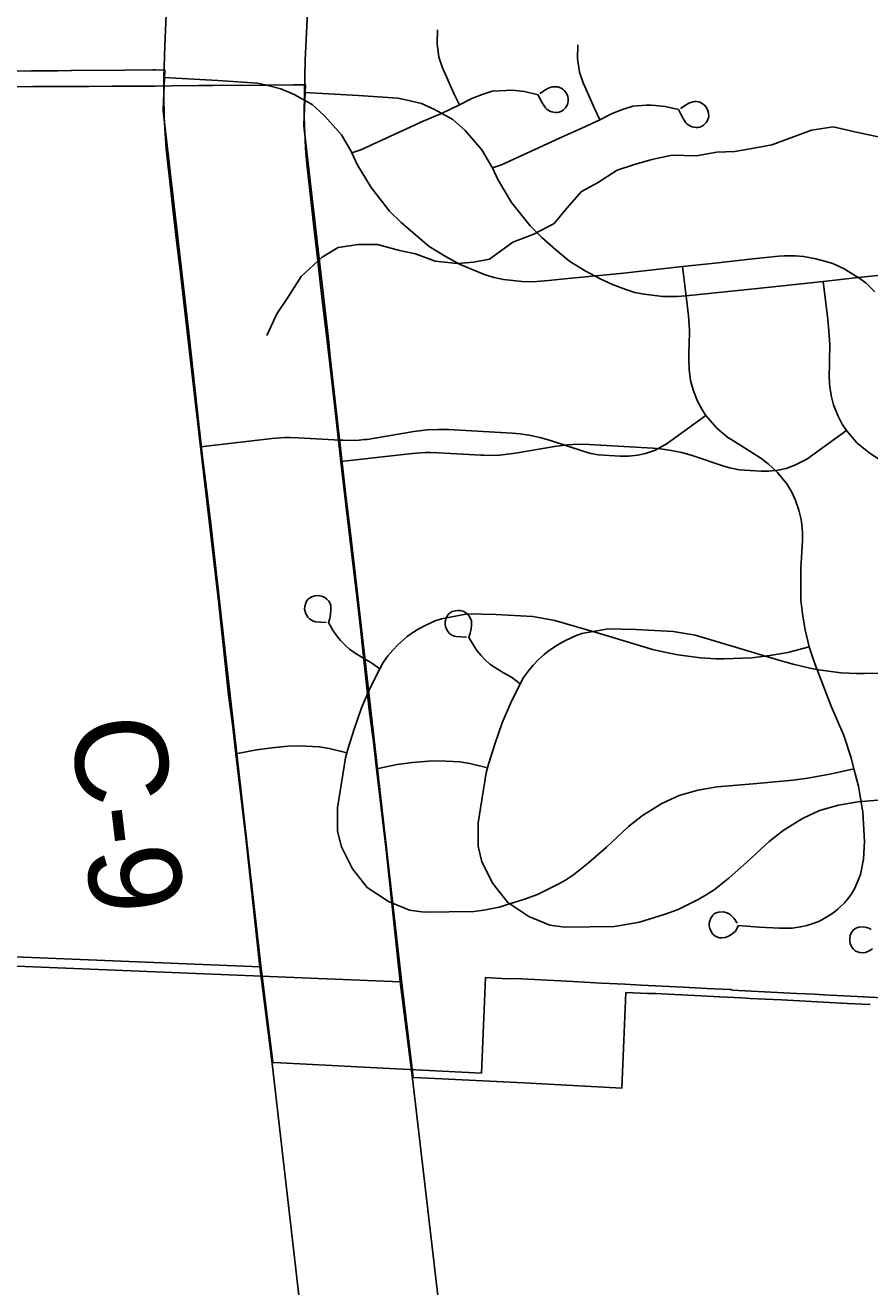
# Model space of a CAD drawing. Extents: x -38.2 to 41.9, y -4 to 24.9.
# Drawn here: x 6.95 to 7.47, y 18.257 to 19.034 of the extents above; entities that cross this region are included whole.
import ezdxf

# ---------------------------------------------------------------- set-up
doc = ezdxf.new("R2010")
doc.units = 0
for name, color, linetype in [('Default', 7, 'Continuous'), ('GM_X_City_Street', 7, 'Continuous'), ('GM_X_County_Road', 7, 'Continuous'), ('GM_X_County_Road_Text', 7, 'Continuous'), ('GM_X_Interstate_Location', 7, 'Continuous'), ('GM_X_Minor_River', 7, 'Continuous'), ('GM_X_State_Location', 7, 'Continuous'), ('GM_X_Township_Road', 7, 'Continuous'), ('GM_X_Township_Road_Text', 7, 'Continuous')]:
    doc.layers.add(name, color=color, linetype=linetype)

msp = doc.modelspace()

# ---------------------------------------------------------------- linework, layer by layer
at = {"layer": 'Default'}
msp.add_lwpolyline([(7.497, 18.43424), (7.46218, 18.436), (7.44131, 18.43708), (7.43595, 18.43734), (7.42495, 18.4379), (7.41694, 18.43831), (7.38512, 18.43992), (7.38471, 18.44022), (7.38362, 18.44027), (7.37894, 18.44049), (7.36978, 18.44096), (7.35502, 18.44171), (7.32916, 18.44303), (7.31911, 18.44354), (7.3097, 18.44401), (7.30457, 18.44427), (7.29085, 18.44497), (7.27963, 18.44554), (7.27144, 18.44596), (7.25156, 18.44697), (7.24675, 18.44696), (7.23335, 18.44764), (7.23212, 18.41809), (7.23092, 18.38882), (7.17044, 18.39194), (7.10733, 18.39511), (7.10279, 18.39533), (7.10252, 18.39535), (7.10249, 18.39557), (7.09519, 18.45511), (7.07983, 18.59072), (7.07899, 18.59787), (7.07242, 18.65558), (7.06436, 18.72708), (7.06082, 18.75528), (7.05954, 18.76639), (7.05681, 18.79004), (7.05223, 18.83156), (7.05142, 18.83892), (7.05024, 18.85002), (7.03554, 18.97766), (7.03508, 18.98152), (7.03511, 18.98205), (7.03617, 19.00643), (7.03589, 19.00644), (7.0302, 19.00651), (7.02868, 19.00649), (7.01151, 19.00636), (6.97904, 19.0061), (6.97833, 19.0061), (6.97031, 19.00602), (6.95401, 19.00585), (6.94344, 19.00575)], dxfattribs=at)
at = {"layer": 'GM_X_City_Street'}
msp.add_lwpolyline([(6.74985, 18.47012), (6.84845, 18.46426), (7.09446, 18.4542)], dxfattribs=at)
at = {"layer": 'GM_X_County_Road'}
for p, q in [((7.06148, 18.7446), (7.05794, 18.77452)), ((7.10206, 18.39474), (7.09446, 18.4542)), ((7.12619, 18.18681), (7.10206, 18.39474))]:
    msp.add_line(p, q, dxfattribs=at)
for points in [[(7.03553, 19.00186), (7.03605, 19.02162), (7.03797, 19.06405), (7.03985, 19.10826), (7.04183, 19.15386), (7.04831, 19.29914)], [(7.05794, 18.77452), (7.05354, 18.81334), (7.05063, 18.83833), (7.04624, 18.87594), (7.04521, 18.88496), (7.04348, 18.8997), (7.0411, 18.92093), (7.03977, 18.9322), (7.03694, 18.95784), (7.03618, 18.96745), (7.03574, 18.97735), (7.03564, 18.98011), (7.03536, 18.98816), (7.03553, 19.00186)], [(7.47009, 18.43109), (7.46542, 18.4313), (7.45626, 18.43177), (7.4415, 18.43252), (7.41564, 18.43384), (7.40559, 18.43435), (7.39618, 18.43483), (7.39104, 18.43508), (7.37733, 18.43578), (7.36611, 18.43636), (7.35792, 18.43677), (7.33803, 18.43778), (7.33323, 18.43777), (7.31983, 18.43845), (7.3186, 18.4089), (7.3174, 18.37963), (7.25692, 18.38275), (7.1938, 18.38592), (7.18927, 18.38615), (7.189, 18.38616), (7.18897, 18.38638), (7.18167, 18.44592), (7.16631, 18.58153), (7.16547, 18.58868), (7.1589, 18.64639), (7.15083, 18.71789), (7.1473, 18.74609), (7.14602, 18.7572), (7.14329, 18.78085), (7.13871, 18.82237), (7.1379, 18.82973), (7.13672, 18.84083), (7.12201, 18.96847), (7.12156, 18.97234), (7.12159, 18.97286), (7.12265, 18.99724), (7.12236, 18.99725), (7.11668, 18.99732), (7.11516, 18.9973), (7.09799, 18.99717), (7.06552, 18.99691), (7.06481, 18.99691), (7.05679, 18.99683), (7.04048, 18.99666), (7.02992, 18.99656), (7.02344, 18.99653), (7.02019, 18.99652), (7.00723, 18.99646), (7.00371, 18.99645), (6.98922, 18.99638), (6.97205, 18.9963), (6.96454, 18.99626), (6.95483, 18.99621), (6.94327, 18.99616)], [(7.09446, 18.4542), (7.08571, 18.53548), (7.0798, 18.58533), (7.078, 18.60202), (7.0753, 18.6217), (7.06938, 18.67779), (7.06148, 18.7446)]]:
    msp.add_lwpolyline(points, dxfattribs=at)
at = {"layer": 'GM_X_Interstate_Location'}
msp.add_lwpolyline([(6.83633, 18.46093), (6.93493, 18.45507), (7.18094, 18.44501)], dxfattribs=at)
at = {"layer": 'GM_X_Minor_River'}
for points in [[(7.43411, 18.96948), (7.41973, 18.96418), (7.40951, 18.96039), (7.39968, 18.9585), (7.38681, 18.95623), (7.37583, 18.95586), (7.36297, 18.95359), (7.34821, 18.95397), (7.33572, 18.95132), (7.32512, 18.9483), (7.31453, 18.94489), (7.30242, 18.93693), (7.29258, 18.93162), (7.2835, 18.92139), (7.27556, 18.91191), (7.26307, 18.90547), (7.25021, 18.90055), (7.23583, 18.88994), (7.22599, 18.88804), (7.21615, 18.88729), (7.20253, 18.88881), (7.19041, 18.89337), (7.18057, 18.89527), (7.16695, 18.89907), (7.15522, 18.89907), (7.14273, 18.89718), (7.13289, 18.89112), (7.12003, 18.87937), (7.11171, 18.86648), (7.1049, 18.85624), (7.09885, 18.84298)], [(7.47498, 18.9653), (7.4606, 18.96834), (7.44736, 18.97138), (7.43411, 18.96948)]]:
    msp.add_lwpolyline(points, dxfattribs=at)
at = {"layer": 'GM_X_State_Location'}
for points in [[(7.30383, 18.97586), (7.30065, 18.98237), (7.29349, 18.99853), (7.29127, 19.00511), (7.29009, 19.01351), (7.29026, 19.02192)], [(7.12201, 18.99267), (7.1552, 18.99074), (7.17955, 18.98907), (7.18435, 18.98816), (7.19397, 18.98578), (7.20211, 18.98212), (7.21321, 18.97599), (7.22081, 18.96912), (7.23117, 18.95733), (7.23671, 18.94789)], [(7.23771, 18.94617), (7.24322, 18.9481), (7.2816, 18.9657), (7.29271, 18.97055), (7.30383, 18.97586), (7.31143, 18.9797), (7.31779, 18.98212), (7.32403, 18.98421), (7.3323, 18.98473), (7.33521, 18.98477), (7.33812, 18.98464), (7.34389, 18.98396), (7.35223, 18.98208)], [(7.35223, 18.98208), (7.35362, 18.97928), (7.35513, 18.97655), (7.35675, 18.97394), (7.35759, 18.97314), (7.35853, 18.97246), (7.35956, 18.97191), (7.36064, 18.97149), (7.36177, 18.97122), (7.36293, 18.9711), (7.36409, 18.97113), (7.36523, 18.97131), (7.36674, 18.97192), (7.36765, 18.97251), (7.3692, 18.97405), (7.36979, 18.97497), (7.37025, 18.97595), (7.37057, 18.97699), (7.37074, 18.97807), (7.37071, 18.97976), (7.37049, 18.98087), (7.36962, 18.98296), (7.36823, 18.98473), (7.36737, 18.98547), (7.36642, 18.98609), (7.3654, 18.98657), (7.36453, 18.98685), (7.36332, 18.98701), (7.36211, 18.987), (7.36089, 18.98685), (7.35971, 18.98655), (7.35858, 18.9861), (7.35751, 18.98552), (7.35679, 18.98501), (7.35341, 18.98283)], [(7.23671, 18.94789), (7.23771, 18.94617), (7.24092, 18.93901), (7.24943, 18.92491), (7.26086, 18.91043), (7.26803, 18.90329), (7.2767, 18.89582), (7.28529, 18.8886), (7.29469, 18.88276), (7.30394, 18.87779), (7.31164, 18.87441), (7.3197, 18.87124), (7.32527, 18.86951), (7.331, 18.86835), (7.34248, 18.86708), (7.3478, 18.8669), (7.35146, 18.86698), (7.35873, 18.86759), (7.36874, 18.86864), (7.40478, 18.87228), (7.44111, 18.87631), (7.46095, 18.87842), (7.48448, 18.88092)], [(7.4451, 18.82437), (7.44519, 18.82764), (7.44538, 18.83711), (7.44472, 18.84593), (7.44404, 18.85279), (7.44111, 18.87631)], [(7.45557, 18.78448), (7.45296, 18.78848), (7.45018, 18.79376), (7.44765, 18.80025), (7.44613, 18.80603), (7.44512, 18.81293), (7.44493, 18.81892), (7.4451, 18.82437)], [(7.14441, 18.76533), (7.18851, 18.77037), (7.19632, 18.77094), (7.19962, 18.77098), (7.20457, 18.77083), (7.23055, 18.76934), (7.2322, 18.76926), (7.23715, 18.76919), (7.24209, 18.76939), (7.24539, 18.76966), (7.24703, 18.76984), (7.25186, 18.77054), (7.27581, 18.77466), (7.28392, 18.77569), (7.29052, 18.776), (7.29713, 18.77586), (7.33631, 18.77362), (7.34117, 18.77321), (7.34771, 18.77226), (7.35417, 18.77086), (7.36051, 18.76901), (7.38064, 18.76235), (7.38462, 18.76123), (7.3895, 18.76035), (7.39275, 18.76005), (7.40283, 18.75947), (7.40779, 18.75944), (7.41354, 18.76008), (7.41838, 18.76117), (7.42384, 18.76309), (7.43116, 18.76694), (7.45557, 18.78448)], [(7.51403, 18.69072), (7.51404, 18.69369), (7.51497, 18.70765), (7.51503, 18.71163), (7.51481, 18.71561), (7.51415, 18.72053), (7.5128, 18.72635), (7.51046, 18.73291), (7.50831, 18.73739), (7.50523, 18.74249), (7.49966, 18.74947), (7.49384, 18.75487), (7.4886, 18.75862), (7.4714, 18.76951), (7.46904, 18.77109), (7.46216, 18.77679), (7.45557, 18.78448)], [(7.22179, 18.65715), (7.21536, 18.65759), (7.21409, 18.65788), (7.21271, 18.65848), (7.21148, 18.65935), (7.21045, 18.66045), (7.20966, 18.66173), (7.20934, 18.66236), (7.20882, 18.66381), (7.2086, 18.66534), (7.20867, 18.66688), (7.20924, 18.66903), (7.20983, 18.6703), (7.21068, 18.6714), (7.21175, 18.6723), (7.21299, 18.67295), (7.21492, 18.67347), (7.21646, 18.67368), (7.21802, 18.67359), (7.21964, 18.67316), (7.22107, 18.67242), (7.22233, 18.67143), (7.2234, 18.67022), (7.22421, 18.66883), (7.22475, 18.66731), (7.22481, 18.66488), (7.22458, 18.66223), (7.22405, 18.65962), (7.22323, 18.65708), (7.22594, 18.65236), (7.22815, 18.64913), (7.2306, 18.6461), (7.23327, 18.64326), (7.23616, 18.64064), (7.2396, 18.63827), (7.24443, 18.63526), (7.24941, 18.63252), (7.25476, 18.6286)], [(7.23458, 18.57675), (7.2354, 18.57973), (7.23909, 18.59136), (7.24362, 18.60452), (7.24874, 18.61641), (7.25476, 18.6286), (7.25681, 18.63251), (7.25982, 18.63659), (7.26282, 18.6401), (7.26604, 18.64342), (7.26948, 18.6465), (7.27176, 18.64837), (7.27525, 18.65091), (7.27892, 18.65319), (7.28273, 18.65522), (7.28888, 18.65807), (7.2927, 18.65941), (7.30882, 18.66244), (7.32618, 18.66192), (7.34899, 18.66076), (7.36247, 18.65839), (7.38937, 18.65054), (7.41252, 18.64348), (7.42272, 18.64053), (7.43307, 18.63817), (7.43829, 18.63722), (7.45222, 18.63534), (7.46176, 18.63481), (7.46653, 18.63477), (7.48371, 18.63533)], [(7.16627, 18.57614), (7.17898, 18.57878), (7.1884, 18.58), (7.19829, 18.58099), (7.20478, 18.58119), (7.20926, 18.58093), (7.21763, 18.58047), (7.22374, 18.57942), (7.23458, 18.57675)], [(7.23458, 18.57675), (7.23375, 18.57379), (7.22882, 18.543), (7.22882, 18.52857), (7.23123, 18.51895), (7.23796, 18.50548), (7.24711, 18.49395), (7.2601, 18.48529), (7.27309, 18.47993), (7.28215, 18.47866), (7.31275, 18.47917), (7.31877, 18.48004), (7.32821, 18.48186), (7.34391, 18.48668), (7.35194, 18.48965), (7.36462, 18.49593), (7.3691, 18.49849), (7.37403, 18.50175), (7.38336, 18.509), (7.39429, 18.51869), (7.40793, 18.53139), (7.4166, 18.53825), (7.42849, 18.54554), (7.43897, 18.55046), (7.45061, 18.55375), (7.46246, 18.55585), (7.48459, 18.55777)], [(7.47069, 18.47716), (7.46933, 18.478), (7.46784, 18.47857), (7.46627, 18.47885), (7.46318, 18.47874), (7.46188, 18.47837), (7.46069, 18.47772), (7.45967, 18.47683), (7.45851, 18.47496), (7.45791, 18.47345), (7.45759, 18.47187), (7.45757, 18.47025), (7.45786, 18.46866), (7.45885, 18.46641), (7.45981, 18.4652), (7.46098, 18.46421), (7.46233, 18.46347), (7.46379, 18.46301), (7.46532, 18.46283), (7.46727, 18.46306), (7.46945, 18.46403), (7.47148, 18.46527)]]:
    msp.add_lwpolyline(points, dxfattribs=at)
at = {"layer": 'GM_X_Township_Road'}
for points in [[(7.21735, 18.98505), (7.21417, 18.99156), (7.20702, 19.00772), (7.20479, 19.0143), (7.20361, 19.0227), (7.20378, 19.03111)], [(7.03553, 19.00186), (7.06872, 18.99993), (7.09308, 18.99826), (7.09787, 18.99735), (7.10749, 18.99497), (7.11564, 18.99131), (7.12673, 18.98518), (7.13433, 18.97831), (7.14469, 18.96652), (7.15023, 18.95708)], [(7.15124, 18.95536), (7.15675, 18.95729), (7.19512, 18.97489), (7.20623, 18.97974), (7.21735, 18.98505), (7.22495, 18.98888), (7.23131, 18.99131), (7.23755, 18.9934), (7.24583, 18.99392), (7.24873, 18.99396), (7.25164, 18.99383), (7.25742, 18.99315), (7.26575, 18.99127)], [(7.26575, 18.99127), (7.26714, 18.98847), (7.26866, 18.98573), (7.27027, 18.98312), (7.27112, 18.98233), (7.27205, 18.98165), (7.27308, 18.9811), (7.27416, 18.98068), (7.27529, 18.98041), (7.27645, 18.98029), (7.27761, 18.98032), (7.27875, 18.9805), (7.28026, 18.98111), (7.28118, 18.9817), (7.28272, 18.98324), (7.28331, 18.98416), (7.28377, 18.98514), (7.28409, 18.98618), (7.28426, 18.98726), (7.28423, 18.98895), (7.28402, 18.99006), (7.28315, 18.99215), (7.28175, 18.99392), (7.2809, 18.99466), (7.27995, 18.99528), (7.27892, 18.99576), (7.27806, 18.99604), (7.27685, 18.9962), (7.27563, 18.99619), (7.27442, 18.99604), (7.27324, 18.99574), (7.2721, 18.99529), (7.27103, 18.99471), (7.27031, 18.9942), (7.26693, 18.99202)], [(7.15023, 18.95708), (7.15124, 18.95536), (7.15444, 18.9482), (7.16295, 18.9341), (7.17438, 18.91962), (7.18155, 18.91248), (7.19023, 18.90501), (7.19881, 18.89779), (7.20822, 18.89194), (7.21746, 18.88698), (7.22516, 18.8836), (7.23322, 18.88043), (7.23879, 18.8787), (7.24452, 18.87754), (7.256, 18.87627), (7.26132, 18.87609), (7.26498, 18.87617), (7.27225, 18.87678), (7.28226, 18.87783), (7.3183, 18.88147), (7.35463, 18.88549), (7.37448, 18.88761), (7.398, 18.89011), (7.41383, 18.89188), (7.41728, 18.89209), (7.42419, 18.89206), (7.4291, 18.89167), (7.43677, 18.89024), (7.4443, 18.88823), (7.44713, 18.88731), (7.45402, 18.88405), (7.46383, 18.87816), (7.46764, 18.87521), (7.47309, 18.8699)], [(7.35862, 18.83356), (7.35872, 18.83683), (7.3589, 18.8463), (7.35825, 18.85512), (7.35756, 18.86198), (7.35463, 18.88549)], [(7.36909, 18.79367), (7.36648, 18.79766), (7.3637, 18.80295), (7.36117, 18.80944), (7.35965, 18.81522), (7.35864, 18.82212), (7.35846, 18.82811), (7.35862, 18.83356)], [(7.05794, 18.77452), (7.10203, 18.77956), (7.10984, 18.78013), (7.11315, 18.78017), (7.11809, 18.78002), (7.14407, 18.77853), (7.14572, 18.77845), (7.15067, 18.77838), (7.15562, 18.77858), (7.15891, 18.77885), (7.16055, 18.77903), (7.16538, 18.77973), (7.18933, 18.78385), (7.19745, 18.78488), (7.20405, 18.78519), (7.21065, 18.78505), (7.24983, 18.78281), (7.25469, 18.7824), (7.26124, 18.78145), (7.26769, 18.78005), (7.27404, 18.7782), (7.29416, 18.77154), (7.29814, 18.77042), (7.30302, 18.76953), (7.30627, 18.76924), (7.31635, 18.76866), (7.32131, 18.76863), (7.32706, 18.76927), (7.3319, 18.77036), (7.33737, 18.77228), (7.34468, 18.77613), (7.36909, 18.79367)], [(7.42755, 18.69991), (7.42757, 18.70287), (7.4285, 18.71684), (7.42855, 18.72082), (7.42834, 18.7248), (7.42768, 18.72972), (7.42632, 18.73554), (7.42399, 18.7421), (7.42184, 18.74658), (7.41875, 18.75168), (7.41318, 18.75866), (7.40736, 18.76406), (7.40212, 18.76781), (7.38492, 18.7787), (7.38256, 18.78028), (7.37569, 18.78598), (7.36909, 18.79367)], [(7.38824, 18.48108), (7.38633, 18.48398), (7.38421, 18.48635), (7.38285, 18.48719), (7.38137, 18.48776), (7.37979, 18.48804), (7.37671, 18.48793), (7.3754, 18.48756), (7.37421, 18.48691), (7.3732, 18.48602), (7.37203, 18.48415), (7.37143, 18.48264), (7.37111, 18.48106), (7.3711, 18.47944), (7.37138, 18.47785), (7.37238, 18.4756), (7.37333, 18.47439), (7.37451, 18.4734), (7.37585, 18.47266), (7.37731, 18.4722), (7.37884, 18.47202), (7.38079, 18.47225), (7.38297, 18.47322), (7.385, 18.47446), (7.38725, 18.4763), (7.38908, 18.47964), (7.40185, 18.47877), (7.41432, 18.4781), (7.42233, 18.47814), (7.4233, 18.47824), (7.4273, 18.47885), (7.43123, 18.47976), (7.43508, 18.48096), (7.43884, 18.48244), (7.44391, 18.48519), (7.44718, 18.48738), (7.45026, 18.48983), (7.45428, 18.49366), (7.45658, 18.49635), (7.45865, 18.49923), (7.46046, 18.50228), (7.462, 18.50547), (7.46408, 18.51106), (7.46604, 18.52053), (7.46664, 18.53146), (7.46558, 18.54945), (7.46288, 18.56542), (7.46017, 18.57625), (7.45849, 18.58291), (7.45399, 18.59675), (7.44621, 18.61471), (7.43891, 18.63345), (7.43559, 18.64211), (7.43267, 18.65134), (7.43022, 18.6617), (7.42873, 18.67012), (7.42745, 18.68011), (7.42755, 18.69991)], [(7.13531, 18.66634), (7.12889, 18.66678), (7.12761, 18.66707), (7.12623, 18.66767), (7.125, 18.66854), (7.12398, 18.66964), (7.12319, 18.67092), (7.12286, 18.67154), (7.12234, 18.673), (7.12212, 18.67453), (7.12219, 18.67607), (7.12276, 18.67822), (7.12335, 18.67949), (7.1242, 18.68059), (7.12527, 18.68149), (7.12651, 18.68214), (7.12844, 18.68266), (7.12998, 18.68287), (7.13154, 18.68278), (7.13316, 18.68234), (7.13459, 18.6816), (7.13586, 18.68062), (7.13692, 18.67941), (7.13773, 18.67802), (7.13827, 18.6765), (7.13833, 18.67407), (7.1381, 18.67141), (7.13757, 18.6688), (7.13675, 18.66627), (7.13947, 18.66155), (7.14167, 18.65832), (7.14412, 18.65529), (7.14679, 18.65245), (7.14968, 18.64983), (7.15312, 18.64746), (7.15795, 18.64445), (7.16294, 18.64171), (7.16828, 18.63779)], [(7.1481, 18.58594), (7.14892, 18.58892), (7.15261, 18.60055), (7.15714, 18.61371), (7.16227, 18.6256), (7.16828, 18.63779), (7.17033, 18.6417), (7.17334, 18.64578), (7.17635, 18.64929), (7.17956, 18.65261), (7.183, 18.65569), (7.18528, 18.65756), (7.18877, 18.6601), (7.19244, 18.66238), (7.19625, 18.66441), (7.2024, 18.66726), (7.20623, 18.6686), (7.22235, 18.67163), (7.23971, 18.67111), (7.26252, 18.66995), (7.27599, 18.66757), (7.30289, 18.65973), (7.32604, 18.65267), (7.33624, 18.64972), (7.34659, 18.64736), (7.35181, 18.6464), (7.36575, 18.64453), (7.37528, 18.644), (7.38006, 18.64396), (7.39724, 18.64452), (7.40835, 18.64586), (7.41938, 18.6478), (7.43267, 18.65134)], [(7.0798, 18.58533), (7.0925, 18.58796), (7.10192, 18.58919), (7.11181, 18.59018), (7.1183, 18.59038), (7.12278, 18.59011), (7.13115, 18.58966), (7.13727, 18.5886), (7.1481, 18.58594)], [(7.1481, 18.58594), (7.14727, 18.58298), (7.14234, 18.55219), (7.14234, 18.53776), (7.14475, 18.52814), (7.15148, 18.51467), (7.16063, 18.50313), (7.17362, 18.49448), (7.18662, 18.48912), (7.19567, 18.48785), (7.22627, 18.48836), (7.23229, 18.48923), (7.24173, 18.49105), (7.25743, 18.49587), (7.26546, 18.49884), (7.27814, 18.50512), (7.28262, 18.50768), (7.28755, 18.51094), (7.29688, 18.51819), (7.30781, 18.52788), (7.32145, 18.54058), (7.33012, 18.54744), (7.34201, 18.55473), (7.3525, 18.55965), (7.36413, 18.56294), (7.37598, 18.56504), (7.39811, 18.56696), (7.42282, 18.56915), (7.43175, 18.57036), (7.44628, 18.57301), (7.46017, 18.57625)]]:
    msp.add_lwpolyline(points, dxfattribs=at)
at = {"layer": 'GM_X_Township_Road_Text'}
for p, q in [((7.14795, 18.73541), (7.14441, 18.76533)), ((7.18854, 18.38555), (7.18094, 18.44501)), ((7.21266, 18.17762), (7.18854, 18.38555))]:
    msp.add_line(p, q, dxfattribs=at)
for points in [[(7.12201, 18.99267), (7.12253, 19.01244), (7.12444, 19.05486), (7.12633, 19.09907), (7.12831, 19.14468), (7.13478, 19.28995)], [(7.14441, 18.76533), (7.14002, 18.80415), (7.13711, 18.82914), (7.13271, 18.86675), (7.13168, 18.87577), (7.12996, 18.89051), (7.12758, 18.91174), (7.12625, 18.92301), (7.12342, 18.94865), (7.12265, 18.95826), (7.12221, 18.96816), (7.12211, 18.97092), (7.12183, 18.97897), (7.12201, 18.99267)], [(7.18094, 18.44501), (7.17219, 18.52629), (7.16627, 18.57614), (7.16448, 18.59283), (7.16178, 18.61251), (7.15586, 18.6686), (7.14795, 18.73541)]]:
    msp.add_lwpolyline(points, dxfattribs=at)

# ---------------------------------------------------------------- texts
at = {"layer": 'GM_X_County_Road_Text'}
msp.add_text('C-9', height=0.056818, rotation=276.6301, dxfattribs=at).set_placement((6.97793, 18.60584))

doc.saveas('drawing.dxf')
